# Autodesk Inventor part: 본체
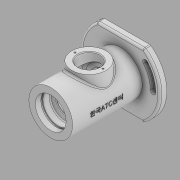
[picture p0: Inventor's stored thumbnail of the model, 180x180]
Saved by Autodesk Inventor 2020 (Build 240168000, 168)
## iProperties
Created: 2022-05
Part Number: 본체
Material: 일반
Document SubType Name: Modeling
Designer: Student
Mass: 254.633 g
Surface Area: 622.213 cm^2
Volume: 254.633 cm^3
Density: 1 g/cm^3
Appearance: 기본값
Author: Student
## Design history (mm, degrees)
sketch "스케치1"
  geometry: L1 (47, 92.583)-(47, -88.297); L2 (69.5, 10.285)-(69.5, 2.285); L3 (69.5, 2.285)-(71, 2.285); L4 (71, 2.285)-(71, -0.715); L5 (71, -0.715)-(69.5, -0.715); L6 (69.5, -0.715)-(69.5, -11.715); L7 (69.5, -11.715)-(65.5, -11.715); L8 (64.5, -12.715)-(64.5, -13.965); L9 (64.5, -13.965)-(65.5, -13.965); L10 (65.5, -13.965)-(65.5, -15.715); L11 (65.5, -15.715)-(64.5, -15.715); L12 (64.5, -15.715)-(64.5, -25.715); L13 (65.5, -26.715)-(71, -26.715); L14 (74, -29.715)-(74, -61.715); L15 (71, -64.715)-(65.5, -64.715); L16 (64.5, -65.715)-(64.5, -75.115); L17 (63.9, -75.715)-(62, -75.715); L18 (62, -75.715)-(62, -77.715); L19 (59, -80.715)-(58, -80.715); L20 (58, -80.715)-(58, -82.715); L21 (58, -82.715)-(61.5, -82.715); L22 (62, -83.215)-(62, -89.715); L23 (62.577, -90.715)-(65.456, -90.715); L24 (67.897, -91.971)-(77, -104.715); L25 (69.5, 10.285)-(79, 10.285); L26 (79, 10.285)-(79, -91.715); L27 (79, -91.715)-(105, -91.715); L28 (105, -91.715)-(105, -101.715); L29 (105, -101.715)-(83, -101.715); L30 (83, -101.715)-(83, -104.715); L31 (83, -104.715)-(77, -104.715); L32 (65.5, -11.715)-(64.5, -12.715); L33 (64.5, -25.715)-(65.5, -26.715); L34 (65.5, -64.715)-(64.5, -65.715); L35 (62, -89.715)-(62.577, -90.715); A1 r 3 centre (71, -29.715) between (74, -29.715) and (71, -26.715); A2 r 3 centre (71, -61.715) between (71, -64.715) and (74, -61.715); A3 r 0.6 centre (63.9, -75.115) between (63.9, -75.715) and (64.5, -75.115); A4 r 3 centre (59, -77.715) between (59, -80.715) and (62, -77.715); A5 r 0.5 centre (61.5, -83.215) between (62, -83.215) and (61.5, -82.715); A6 r 3 centre (65.456, -93.715) between (67.897, -91.971) and (65.456, -90.715); 11 further points
  constraints: 70 end point, 24 point on line, 23 perpendicular, 12 point on circle, 12 tangent, 6 centre point, 2 horizontal, 2 vertical, 1 equal radius
  dimensions: "d0" = 47 distance from line of point (0, 0) L1; "d3" = 22 diameter of L20 L1; "d4" = 48 diameter of L4 L1; "d6" = 45 diameter of L6 L1; "d7" = 45 diameter of L2 L1; "d8" = 35 diameter of L8 L1; "d10" = 54 diameter of L14 L1; "d11" = 30 diameter of L18 L1; "d12" = 40 diameter of point (67, -90.715) L1; "d13" = 30 diameter of L22 L1; "d14" = 60 diameter of L24.end L1; "d15" = 72 diameter of L30.end L1; "d16" = 64 diameter of L26 L1; "d17" = 8 distance of L2.start L2.end; "d18" = 3 distance of L3.end L4.end; "d20" = 37 diameter of L10 L1; "d21" = 1.75 distance of L9.end L10.end; "d22" = 4 vertical distance of L10.end point (64.5, -11.715); "d23" = 11 distance of L11.end point (64.5, -26.715); "d24" = 38 distance of point (74, -26.715) point (74, -64.715); "d25" = 11 distance of point (64.5, -64.715) point (64.5, -75.715); "d26" = 5 distance of L17.end point (62, -80.715); "d27" = 14 vertical distance of L24.end point (67, -90.715); "d28" = 115 distance from line of L24.end L25; "d29" = 3 distance of L29.end L30.end; "d30" = 13 distance from line of L30.end L27; "d31" = 116 diameter of L28 L1; "d32" = 8 distance of point (62, -90.715) point (62, -82.715); "d54" = 101.71474 distance from line of point (0, 0) L29; "d55" = 194.29758 distance from line of L1.start L29; "d56" = 13.41793 distance from line of L1.end L29; "d125" = 1 distance of L7.end point (64.5, -11.715); "d126" = 1 distance of L8.start point (64.5, -11.715) (= d125); "d127" = 1 distance of L12.end point (64.5, -26.715); "d128" = 1 distance of L13.start point (64.5, -26.715) (= d127); "d129" = 3 radius of A1; "d130" = 1 distance of L15.end point (64.5, -64.715); "d131" = 1 distance of L16.start point (64.5, -64.715) (= d130); "d132" = 0.6 radius of A3; "d133" = 3 radius of A4; "d134" = 0.5 radius of A5; "d135" = 1 distance of L22.end point (62, -90.715); "d136" = 30 deg angle of L22 L35; "d137" = 3 radius of A6; "d167" = 23 vertical distance of L8.start L2.start
revolve "회전1" sketch "스케치1" stored, may be unused: angle "d57" = 90 deg
sketch "스케치2"
  geometry: L1 (-48.645, 85.087)-(48.645, 85.087); L2 (48.645, 85.087)-(48.645, 47); L3 (48.645, 47)-(-48.645, 47); L4 (-48.645, 47)-(-48.645, 85.087); C1 r 11 at (0, 0) reference; 2 further points
  constraints: 8 end point, 2 parallel, 1 horizontal, 1 midpoint, 1 perpendicular, 1 vertical alignment
  dimensions: "d59" = 47 distance from line of C1.centre L3; "d63" = 38.08713 distance of L1.end L2.end; "d64" = 97.29056 distance of L1.start L1.end
extrude "돌출1" cut sketch "스케치2" distance "d60" = 10; taper "d61" = 0 deg
node "작업 평면1"
sketch "스케치7"
  geometry: 1 further point
sketch "스케치8"
  geometry: C1 r 32 at (0, 0) reference; 1 further point
hole "구멍3" sketch "스케치8" at (0, 0) diameter "d94" = 43.376; stored, may be unused: countersink angle "d98" = 90 deg, drill point angle "d100" = 118 deg; dims "d95" = 8, "d96" = 4, "d97" = 2, "d99" = 22
node "작업 평면2"
sketch "스케치9"
  geometry: L1 (-32, 10.285)-(32, 10.285) reference; C1 r 25 at (0, -45.715); 1 further point
  constraints: 1 centre point, 1 vertical alignment
  dimensions: "d102" = 25 radius of C1; "d103" = 56 distance from line of C1.centre L1
extrude "돌출4" join sketch "스케치9" stored distance "d104" = 4.4; taper "d105" = 5 deg
sketch "스케치10"
  geometry: C1 r 25 at (0, 0) reference; 1 further point
hole "구멍4" sketch "스케치10" at (0, 0) diameter "d106" = 32; stored, may be unused: countersink angle "d110" = 90 deg, drill point angle "d112" = 118 deg; dims "d107" = 8, "d108" = 4, "d109" = 2, "d111" = 22
sketch "스케치11"
  geometry: C1 r 16 at (0, 0) reference; 2 further points
  constraints: 1 horizontal alignment
  dimensions: "d113" = 20.5 distance of C1.centre point (-20.5, 0)
hole "구멍5" sketch "스케치11" at (-20.5, 0) diameter "d114" = 2.459; stored, may be unused: countersink angle "d118" = 90 deg, drill point angle "d120" = 118 deg; dims "d115" = 6, "d116" = 4, "d117" = 2, "d119" = 8.8
fillet "모깎기1" dims "d124" = 3
node "작업 평면3"
sketch "스케치12"
  geometry: L1 (0, -101.715)-(94, -101.715) reference; L2 (15, 10.285)-(79, 10.285) reference; L3 (94, -101.715)-(94, -91.715) reference; 2 further points
  constraints: 1 other
  dimensions: "d139" = 62 distance from line of L1 point (47, -39.715); "d140" = 47 distance from line of point (47, -39.715) L3
feature "엠보싱1" sketch "스케치12" dims "d141" = 0.5, "d142" = 0
fillet "모깎기2" dims "d143" = 3
fillet "모깎기3" dims "d144" = 3
sketch "스케치13"
  geometry: L1 (33, -44)-(69.77, -13.146); L2 (33, -44)-(81, -44); L3 (33, -44)-(-3.77, -74.854); L4 (33, -44)-(-15, -44); C1 r 20.897 at (33, -44) reference; A1 r 48 centre (33, -44) between (81, -44) and (69.77, -13.146); A2 r 52 centre (33, -44) between (85, -44) and (72.834, -10.575); A3 r 44 centre (33, -44) between (77, -44) and (66.706, -15.717); A4 r 4 centre (81, -44) between (77, -44) and (85, -44); A5 r 4 centre (69.77, -13.146) between (72.834, -10.575) and (66.706, -15.717); A6 r 48 centre (33, -44) between (-15, -44) and (-3.77, -74.854); A7 r 52 centre (33, -44) between (-19, -44) and (-6.834, -77.425); A8 r 44 centre (33, -44) between (-11, -44) and (-0.706, -72.283); A9 r 4 centre (-15, -44) between (-11, -44) and (-19, -44); A10 r 4 centre (-3.77, -74.854) between (-6.834, -77.425) and (-0.706, -72.283); 1 further point
  constraints: 20 point on circle, 10 centre point, 8 end point, 8 tangent, 2 coincident, 1 concentric, 1 horizontal
  dimensions: "d145" = 48 radius of A1; "d146" = 40 deg angle of L2 L1; "d147" = 4 radius of A5; "d148" = 48 radius of A6; "d149" = 40 deg angle of L4 L3; "d150" = 4 radius of A10 (derived); "d151" = 140 deg angle of L2 L3
extrude "돌출5" cut sketch "스케치13" distance "d152" = 4.4; taper "d153" = 0 deg
sketch "스케치14"
  geometry: A1 r 4 centre (-15, -44) between (-11, -44) and (-19, -44) reference; A2 r 52 centre (33, -44) between (-19, -44) and (-6.834, -77.425) reference; A3 r 4 centre (-3.77, -74.854) between (-6.834, -77.425) and (-0.706, -72.283) reference; A4 r 44 centre (33, -44) between (-11, -44) and (-0.706, -72.283) reference; A5 r 52 centre (33, -44) between (85, -44) and (72.834, -10.575) reference; A6 r 4 centre (69.77, -13.146) between (72.834, -10.575) and (66.706, -15.717) reference; A7 r 44 centre (33, -44) between (77, -44) and (66.706, -15.717) reference; A8 r 4 centre (81, -44) between (77, -44) and (85, -44) reference; A9 r 48 centre (33, -44) between (-15, -44) and (-3.77, -74.854); A10 r 50.25 centre (33, -44) between (-17.25, -44) and (-5.494, -76.3); A11 r 45.75 centre (33, -44) between (-12.75, -44) and (-2.047, -73.408); A12 r 2.25 centre (-15, -44) between (-12.75, -44) and (-17.25, -44); A13 r 2.25 centre (-3.77, -74.854) between (-5.494, -76.3) and (-2.047, -73.408); A14 r 48 centre (33, -44) between (81, -44) and (69.77, -13.146); A15 r 50.25 centre (33, -44) between (83.25, -44) and (71.494, -11.7); A16 r 45.75 centre (33, -44) between (78.75, -44) and (68.047, -14.592); A17 r 2.25 centre (81, -44) between (78.75, -44) and (83.25, -44); A18 r 2.25 centre (69.77, -13.146) between (71.494, -11.7) and (68.047, -14.592); 1 further point
  constraints: 20 point on circle, 10 centre point, 8 tangent, 2 coincident, 1 concentric
  dimensions: "d154" = 2.25 radius of A12
extrude "돌출6" cut sketch "스케치14" extent not by distance; stored distance "d155" = 0; taper "d156" = 0 deg
sketch "스케치15"
  geometry: A1 r 2.25 centre (-3.77, -16.146) between (-2.047, -17.592) and (-5.494, -14.7) reference; A2 r 2.25 centre (69.77, -77.854) between (68.047, -76.408) and (71.494, -79.3) reference; 1 further point
hole "구멍6" sketch "스케치15" at (-3.77, -16.146), (69.77, -77.854) diameter "d157" = 8; stored, may be unused: countersink angle "d161" = 90 deg, drill point angle "d163" = 118 deg; dims "d158" = 8, "d159" = 4, "d160" = 2, "d162" = 11
chamfer "모따기1" distance "d164" = 1; stored, may be unused: second distance "d165" = 2, angle "d166" = 45 deg
node "솔리드1"
mirror "미러1"
pattern_circular "원형 패턴1" dims angle "d122" = 360 deg
node "투영된 루프3"
node "투영된 루프4"
node "투영된 루프5"
feature "A9D066F2-1C7D-4E18-AEED-F7BC21143FA4" dims "d94" = 43.376, "d95" = 8, "d96" = 4, "d97" = 2, "d98" = 90 deg, "d99" = 22, "d100" = 118 deg
other parameters: "d62" = -47, "d101" = 85, "d138" = 33
